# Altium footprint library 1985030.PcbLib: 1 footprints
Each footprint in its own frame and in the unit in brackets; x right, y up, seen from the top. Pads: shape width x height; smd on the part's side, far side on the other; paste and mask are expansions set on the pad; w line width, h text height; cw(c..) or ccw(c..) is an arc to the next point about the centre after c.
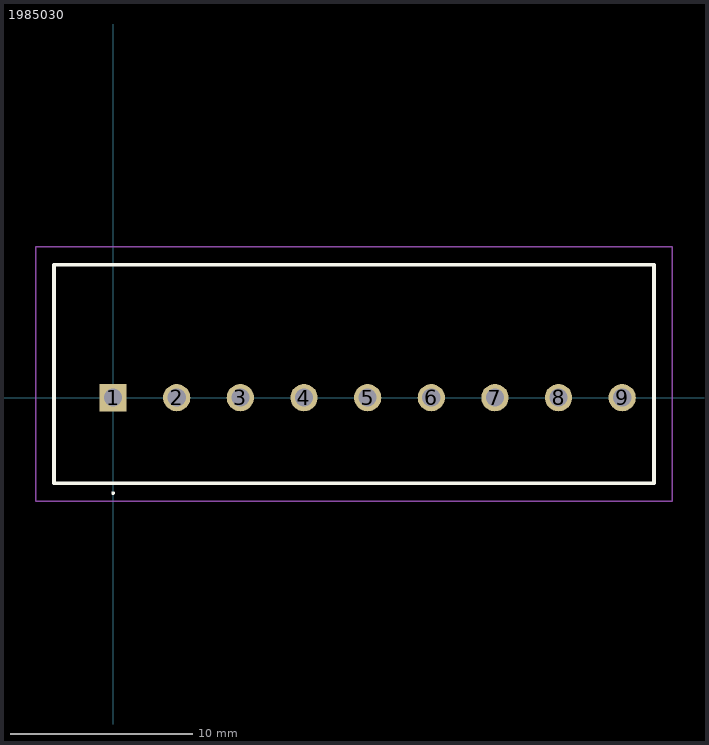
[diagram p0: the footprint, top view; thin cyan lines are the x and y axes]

## 1985030 [mm]
pads (9):
  rect 1.5x1.5 hole 1: 1(0,0)
  round 1.5 hole 1: 2(3.5,0) 3(7,0) 4(10.5,0) 5(14,0) 6(17.5,0) 7(21,0) 8(24.5,0) 9(28,0)
Top Overlay:
  lines w0.1: 0,-5.3 cw(c0,-5.25) 0,-5.2 ; 0,-5.3 0,-5.3 ; 0,-5.3 ccw(c0,-5.25) 0,-5.2 ; 0,-5.2 0,-5.2
  lines w0.2: -3.25,-4.7 29.75,-4.7 29.75,7.3 -3.25,7.3 -3.25,-4.7
Mechanical 15:
  lines w0.1: -3.25,-4.7 29.75,-4.7 29.75,7.3 -3.25,7.3 -3.25,-4.7
Mechanical 20:
  lines w0.1: -4.25,-5.7 30.75,-5.7 30.75,8.3 -4.25,8.3 -4.25,-5.7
